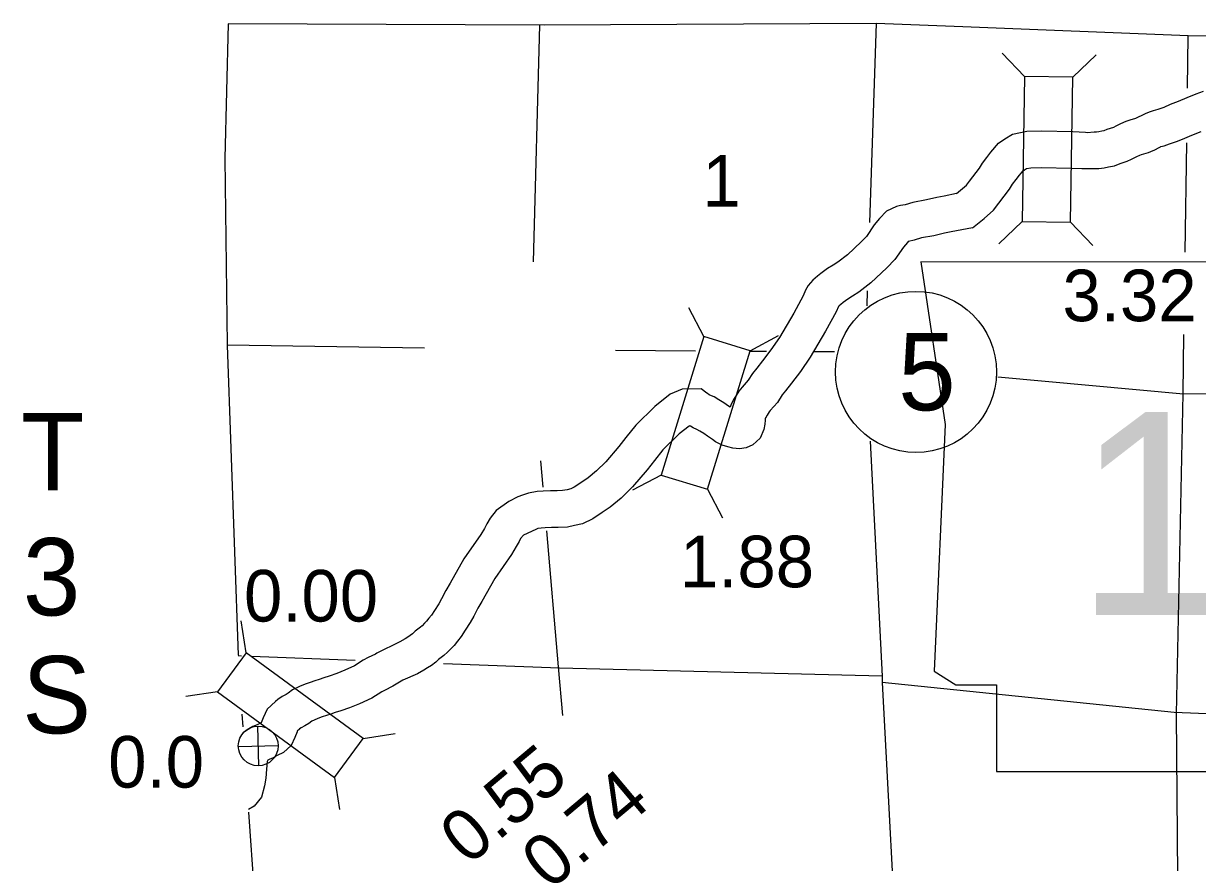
# Model space of a CAD drawing. Extents: x 369523 to 838377, y 495025 to 936819.
# Drawn here: x 624840 to 644076, y 904597 to 918342 of the extents above; entities that cross this region are included whole.
import ezdxf

# ---------------------------------------------------------------- set-up
doc = ezdxf.new("R2010")
doc.units = 0
for name, color, linetype in [('21', 7, 'Continuous'), ('22', 7, 'Continuous'), ('DSN_BRDG_Annotation', 7, 'Continuous'), ('DSN_DRFT_Common-Annotations', 7, 'Continuous'), ('DSN_DRFT_Common-Line', 7, 'Continuous'), ('DSN_DRFT_Junk-No-Plot', 7, 'Continuous'), ('Level 1', 7, 'Continuous'), ('Level 15', 7, 'Continuous'), ('Level 21', 7, 'Continuous'), ('Level 22', 7, 'Continuous'), ('Level 6', 7, 'Continuous')]:
    doc.layers.add(name, color=color, linetype=linetype)

msp = doc.modelspace()

# ---------------------------------------------------------------- linework, layer by layer
at = {"layer": '21'}
msp.add_line((625125, 909315), (625125, 909315), dxfattribs=at)
at = {"layer": '22'}
msp.add_lwpolyline([(639541, 914438), (639941, 911773), (639763, 907732), (640118, 907510), (640784, 907510), (640784, 906089), (646380, 906089), (646646, 906666), (646558, 907598), (646691, 908664), (647179, 909508), (647490, 910130), (647934, 910796), (648201, 911507), (648423, 912084), (648822, 912572), (648911, 912883), (648734, 913105), (647357, 913105), (647668, 913727), (647712, 914127), (647528, 914434)], close=True, dxfattribs=at)
at = {"layer": 'DSN_DRFT_Common-Annotations'}
for p, q in [((628694, 906182), (628679, 906833)), ((628361, 906500), (629012, 906515))]:
    msp.add_line(p, q, dxfattribs=at)
msp.add_circle((628686, 906507), 326, dxfattribs=at)
at = {"layer": 'DSN_DRFT_Common-Line'}
msp.add_circle((639463, 912634), 1320, dxfattribs=at)
at = {"layer": 'Level 1'}
for points in [[(642269, 916558), (642385, 916567), (642418, 916568), (642458, 916572), (642507, 916582), (642548, 916589), (642597, 916609), (642702, 916646), (642743, 916664), (642822, 916703), (642906, 916742), (642971, 916765), (643063, 916793), (643087, 916803), (643120, 916816), (643158, 916837), (643221, 916870), (643289, 916897), (643357, 916915), (643429, 916939), (643529, 916972), (643635, 917020), (643762, 917068), (643905, 917128), (644052, 917189), (644176, 917236)], [(640128, 915557), (640193, 915609), (640293, 915696), (640341, 915760), (640501, 915972), (640552, 916052), (640623, 916148), (640689, 916236), (640816, 916384), (640921, 916450), (641045, 916529), (641279, 916578), (641515, 916582), (642031, 916573), (642239, 916561), (642269, 916558)], [(642181, 915964), (642398, 915967), (642460, 915969), (642546, 915978), (642620, 915993), (642715, 916010), (642809, 916048), (642921, 916088), (642995, 916119), (643080, 916162), (643131, 916185), (643158, 916195), (643271, 916228), (643313, 916247), (643378, 916271), (643447, 916311), (643470, 916323), (643476, 916325), (643530, 916340), (643617, 916369), (643748, 916412), (643867, 916466), (643984, 916511), (644136, 916574)], [(640389, 914997), (640578, 915149), (640733, 915284), (640819, 915396), (640995, 915630), (641047, 915712), (641104, 915789), (641158, 915860), (641213, 915925), (641241, 915943), (641275, 915964), (641346, 915979), (641514, 915982), (642009, 915973), (642181, 915964)], [(640128, 915557), (639924, 915516), (639805, 915492), (639634, 915453), (639412, 915411), (639288, 915374), (639212, 915359), (639146, 915342), (638979, 915270), (638868, 915149), (638780, 915041), (638650, 914854), (638564, 914763), (638339, 914551), (638181, 914432), (638104, 914382), (638011, 914327), (637902, 914246), (637847, 914202), (637773, 914138), (637699, 914048), (637655, 913971), (637617, 913882), (637460, 913597), (637225, 913199), (637086, 912996), (636948, 912817), (636854, 912693), (636787, 912610), (636713, 912497), (636613, 912383), (636561, 912316), (636519, 912246), (636486, 912196), (636433, 912104), (636419, 912055), (636389, 912075), (636315, 912128), (636232, 912177), (636156, 912224), (636086, 912255), (636077, 912260), (636047, 912278), (636037, 912284), (635941, 912359), (635634, 912350), (635438, 912267), (635184, 912068), (634872, 911759), (634709, 911558), (634594, 911411), (634382, 911162), (634227, 911012), (634092, 910898), (633988, 910829), (633864, 910746), (633806, 910717), (633746, 910705), (633674, 910689), (633582, 910685), (633474, 910684), (633357, 910679), (633257, 910673), (633116, 910649), (633018, 910614), (632938, 910585)], [(640389, 914997), (640042, 914928), (639930, 914905), (639756, 914866), (639556, 914828), (639434, 914791), (639343, 914773), (639338, 914772), (639335, 914770), (639322, 914756), (639259, 914679), (639117, 914474), (638988, 914338), (638726, 914092), (638524, 913940), (638421, 913873), (638345, 913827), (638269, 913771), (638230, 913740), (638203, 913716), (638196, 913708), (638194, 913704), (638157, 913618), (637982, 913301), (637732, 912876), (637571, 912642), (637424, 912452), (637325, 912322), (637273, 912257), (637193, 912134), (637076, 912001), (637058, 911978), (637027, 911926), (636995, 911878), (636993, 911875), (636991, 911844), (636987, 911780), (636968, 911693), (636912, 911551), (636790, 911437), (636679, 911391), (636574, 911375), (636464, 911385), (636382, 911405), (636285, 911434), (636179, 911490), (636130, 911526), (636048, 911581), (635988, 911624), (635921, 911663), (635875, 911692), (635815, 911718), (635771, 911744), (635759, 911751), (635746, 911746), (635581, 911617), (635318, 911356), (635178, 911184), (635058, 911032), (634821, 910751), (634630, 910567), (634452, 910416), (634321, 910330), (634166, 910225), (633999, 910143), (633868, 910118), (633753, 910092), (633598, 910085), (633490, 910084), (633387, 910079), (633324, 910076), (633269, 910067), (633237, 910055)], [(632938, 910585), (632791, 910513), (632584, 910363), (632484, 910238), (632432, 910144), (632392, 910071), (632333, 909971), (632053, 909571), (631831, 909174), (631759, 909053), (631690, 908919), (631643, 908837), (631572, 908724), (631526, 908651), (631482, 908599), (631443, 908549), (631412, 908518), (631372, 908476), (631344, 908451), (631260, 908385), (631212, 908344), (631173, 908314), (631138, 908291), (631092, 908262), (631006, 908213), (630630, 908026)], [(633237, 910055), (633031, 909961), (632985, 909905), (632959, 909856), (632913, 909773), (632837, 909645), (632562, 909252), (632351, 908874), (632284, 908762), (632217, 908632), (632157, 908528), (632079, 908404), (632012, 908297), (631950, 908224), (631895, 908152), (631841, 908097), (631786, 908041), (631727, 907989), (631641, 907922), (631594, 907881), (631523, 907825), (631462, 907786), (631400, 907746), (631294, 907687), (631057, 907583)], [(630630, 908026), (630606, 908012), (630488, 907953), (630408, 907913), (630262, 907817), (630105, 907749), (629972, 907692), (629850, 907652), (629760, 907622), (629684, 907597), (629613, 907573), (629538, 907548), (629453, 907517), (629360, 907480), (629246, 907424), (629174, 907369), (629145, 907351), (629081, 907316), (629005, 907266), (628968, 907234), (628830, 907111)], [(631057, 907583), (630894, 907485), (630756, 907417), (630709, 907393), (630549, 907288), (630343, 907198), (630184, 907130), (630040, 907083), (629948, 907052), (629874, 907028), (629805, 907004), (629734, 906981), (629665, 906956), (629603, 906931), (629563, 906911), (629514, 906874), (629449, 906834), (629391, 906802), (629365, 906785), (629363, 906783), (629326, 906750)], [(628830, 907111), (628766, 906967), (628737, 906887), (628670, 906854), (628597, 906823), (628523, 906777), (628435, 906720)], [(629326, 906750), (629322, 906740), (629286, 906644), (629228, 906513), (629102, 906398), (628999, 906348), (628922, 906309), (628875, 906289), (628846, 906271), (628830, 906249), (628830, 906247), (628824, 906127), (628810, 905979), (628790, 905853), (628742, 905665), (628619, 905521), (628528, 905465)]]:
    msp.add_lwpolyline(points, dxfattribs=at)
at = {"layer": 'Level 15'}
for points in [[(638811, 918342), (638701, 915081)], [(638664, 913960), (638656, 913716)], [(638711, 911502), (638907, 907652), (638908, 907544), (639187, 902295)]]:
    msp.add_lwpolyline(points, dxfattribs=at)
at = {"layer": 'Level 21'}
for p, q in [((641243, 917475), (640876, 917854)), ((642034, 917461), (642414, 917828)), ((641201, 915099), (640822, 914732)), ((641993, 915085), (642360, 914706)), ((635988, 913215), (635741, 913682)), ((636745, 912982), (637212, 913228)), ((635288, 910945), (634821, 910698)), ((636045, 910711), (636291, 910244)), ((628489, 908033), (628409, 908555)), ((628021, 907394), (627499, 907314)), ((630406, 906629), (630928, 906710)), ((629938, 905990), (630018, 905468))]:
    msp.add_line(p, q, dxfattribs=at)
for points in [[(641993, 915085), (642034, 917461), (641243, 917475), (641201, 915099)], [(636045, 910711), (636745, 912982), (635988, 913215), (635288, 910945)], [(630406, 906629), (628489, 908033), (628021, 907394), (629938, 905990)]]:
    msp.add_lwpolyline(points, close=True, dxfattribs=at)
at = {"layer": 'Level 22'}
for points in [[(633293, 918312), (633193, 914436)], [(643911, 917284), (643923, 918139)], [(643873, 914598), (643898, 916385)], [(643841, 912275), (643854, 913246)], [(631413, 913023), (628180, 913075)], [(635849, 912976), (634539, 912985)], [(637012, 912969), (636752, 912970)], [(638127, 912961), (637797, 912963)], [(670351, 912810), (664932, 912677), (659710, 912471), (654381, 912279), (649169, 912279), (643845, 912269)], [(643845, 912269), (640805, 912549)], [(643852, 899340), (643852, 899362), (643776, 901698), (643732, 907031), (643841, 912275)], [(633312, 911179), (633349, 910746)], [(633411, 910029), (633603, 907803), (633671, 907003)], [(628411, 907979), (628356, 907981)], [(630272, 907908), (628576, 907972)], [(638907, 907652), (633622, 907779), (631720, 907852)], [(643693, 907052), (638908, 907544)], [(670304, 907639), (664925, 907367), (659610, 907181), (654331, 907002), (649137, 906828), (643693, 907052)]]:
    msp.add_lwpolyline(points, dxfattribs=at)
at = {"layer": 'Level 6'}
for points in [[(640230, 918286), (638811, 918342), (633369, 918312), (628196, 918335), (628141, 916128)], [(645828, 918131), (643923, 918139), (640230, 918286)], [(628141, 916128), (628180, 913075), (628355, 907992)], [(628420, 907029), (628434, 906821)], [(628528, 905424), (628617, 904099)]]:
    msp.add_lwpolyline(points, dxfattribs=at)

# ---------------------------------------------------------------- texts
at = {"layer": '21'}
for s, p in [('T', (624802, 910693)), ('3', (624830, 908645)), ('S', (624818, 906713))]:
    msp.add_text(s, height=1267, dxfattribs=at).set_placement(p)
at = {"layer": '22'}
msp.add_text('171', height=3326.4, dxfattribs=at).set_placement((642073, 908652))
at = {"layer": 'DSN_BRDG_Annotation'}
msp.add_text('0.0', height=844.8, dxfattribs=at).set_placement((626228, 905824))
at = {"layer": 'DSN_DRFT_Common-Line'}
msp.add_text('5', height=1267, dxfattribs=at).set_placement((639171, 912005))
at = {"layer": 'DSN_DRFT_Junk-No-Plot'}
for s, p in [('3.32', (641863, 913465)), ('1.88', (635595, 909106)), ('0.00', (628453, 908545))]:
    msp.add_text(s, height=844.8, dxfattribs=at).set_placement(p)
for s, p in [('0.55', (632125, 904530)), ('0.74', (633463, 904126))]:
    msp.add_text(s, height=844.8, rotation=40, dxfattribs=at).set_placement(p)
at = {"layer": 'Level 22'}
msp.add_text('1', height=845, dxfattribs=at).set_placement((635962, 915340))

doc.saveas('drawing.dxf')
